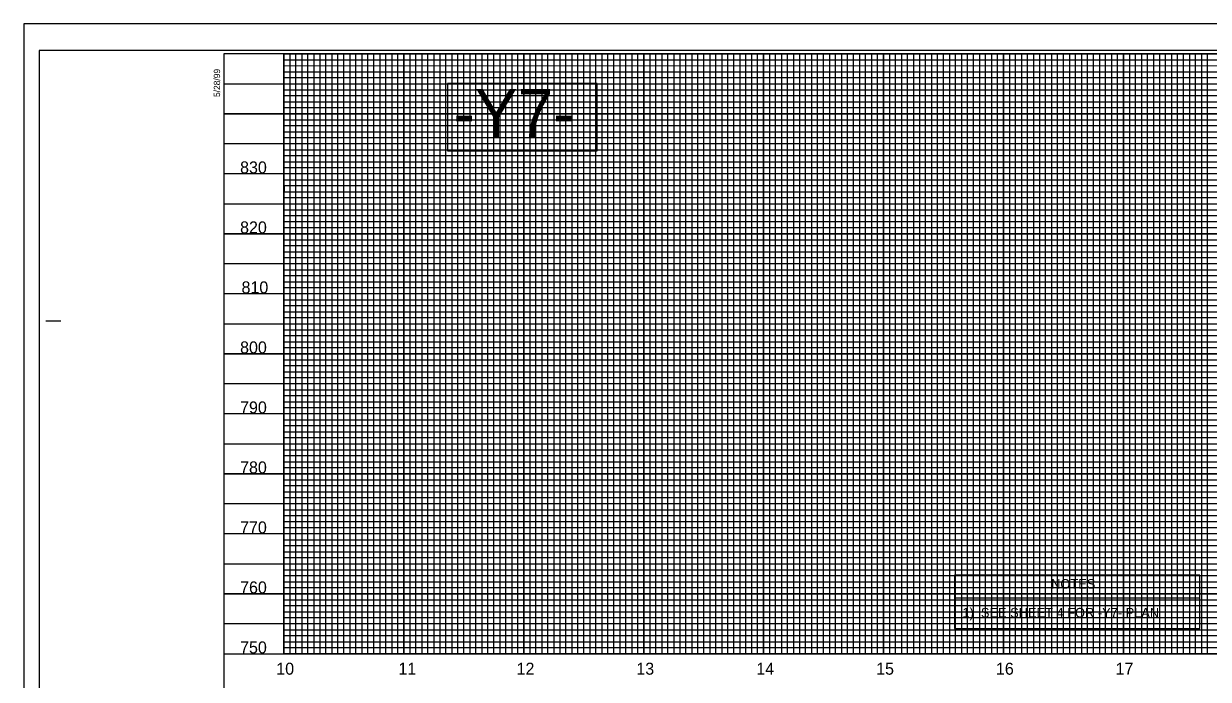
# Model space of a CAD drawing. Extents: x 600491 to 602382, y -54561 to -53461.
# Drawn here: x 600491 to 601479, y -54007 to -53461 of the extents above; entities that cross this region are included whole.
import ezdxf

# ---------------------------------------------------------------- set-up
doc = ezdxf.new("R2010")
doc.units = 0
for name, color, linetype in [('Default', 7, 'Continuous'), ('Exist Vertical Profile Horizontal Axis Label Major', 7, 'Continuous'), ('Exist Vertical Profile Vertical Axis Label', 7, 'Continuous'), ('Prop DSN Text', 7, 'Continuous'), ('Prop Grid Mask', 7, 'Continuous'), ('Prop VPI Label', 7, 'Continuous'), ('Sheet Cutting Line CELL', 7, 'Continuous'), ('Sheet DOT Grid CELL', 7, 'Continuous'), ('Sheet Layout Profile Border Port 1', 7, 'Continuous'), ('Sheet Plot Border Inside CELL', 7, 'Continuous'), ('Sheet Plot Border Outside CELL', 7, 'Continuous'), ('Sheet Profile CELL', 7, 'Continuous'), ('Sheet Profile Grid Major CELL', 7, 'Continuous'), ('Sheet Profile Grid Middle CELL', 7, 'Continuous'), ('Sheet Profile Grid Minor CELL', 7, 'Continuous')]:
    doc.layers.add(name, color=color, linetype=linetype)

msp = doc.modelspace()

# ---------------------------------------------------------------- linework, layer by layer
at = {"layer": 'Default'}
msp.add_lwpolyline([(600708.27, -53985.99), (601508.27, -53985.99), (601508.27, -53485.99), (600708.27, -53485.99)], close=True, dxfattribs=at)
at = {"layer": 'Prop Grid Mask'}
msp.add_line((601108.22, -53485.99), (601208.22, -53485.99), dxfattribs=at)
for points in [[(600844.71, -53566.95), (600969.5, -53566.95), (600969.5, -53510.89), (600844.71, -53510.89)], [(601267.49, -53964.91), (601471.84, -53964.91), (601471.84, -53920.63), (601267.49, -53920.63)], [(601267.49, -53939.34), (601471.84, -53939.34), (601471.84, -53920.63), (601267.49, -53920.63)]]:
    msp.add_lwpolyline(points, close=True, dxfattribs=at)
at = {"layer": 'Sheet Cutting Line CELL'}
for p, q in [((602175.27, -53460.99), (600491.27, -53460.99)), ((600491.27, -53460.99), (600491.27, -54560.99))]:
    msp.add_line(p, q, dxfattribs=at)
at = {"layer": 'Sheet DOT Grid CELL'}
for p, q in [((600708.27, -53985.99), (600708.27, -53485.99)), ((600758.27, -53985.99), (600758.27, -53485.99)), ((600808.27, -53985.99), (600808.27, -53485.99)), ((600858.27, -53985.99), (600858.27, -53485.99)), ((600908.27, -53985.99), (600908.27, -53485.99)), ((600958.27, -53985.99), (600958.27, -53485.99)), ((601008.27, -53985.99), (601008.27, -53485.99)), ((601058.27, -53985.99), (601058.27, -53485.99)), ((601108.27, -53985.99), (601108.27, -53485.99)), ((601158.27, -53985.99), (601158.27, -53485.99)), ((601208.27, -53985.99), (601208.27, -53485.99)), ((601258.27, -53985.99), (601258.27, -53485.99)), ((601308.27, -53985.99), (601308.27, -53485.99)), ((601358.27, -53985.99), (601358.27, -53485.99)), ((601408.27, -53985.99), (601408.27, -53485.99)), ((601458.27, -53985.99), (601458.27, -53485.99)), ((601958.22, -53535.99), (600658.27, -53535.99)), ((601958.22, -53585.99), (600658.27, -53585.99)), ((602158.27, -53635.99), (600658.27, -53635.99)), ((602158.27, -53685.99), (600658.27, -53685.99)), ((602158.27, -53735.99), (600658.27, -53735.99)), ((602158.27, -53785.99), (600658.27, -53785.99)), ((602158.27, -53835.99), (600658.27, -53835.99)), ((602158.27, -53885.99), (600658.27, -53885.99)), ((602158.27, -53935.99), (600658.27, -53935.99))]:
    msp.add_line(p, q, dxfattribs=at)
at = {"layer": 'Sheet Layout Profile Border Port 1'}
msp.add_lwpolyline([(601508.27, -53985.99), (600708.27, -53985.99), (600708.27, -53485.99), (601508.27, -53485.99)], close=True, dxfattribs=at)
at = {"layer": 'Sheet Plot Border Inside CELL'}
msp.add_lwpolyline([(600504.27, -54538.54), (602170.77, -54538.54), (602170.77, -53483.44), (600504.27, -53483.44)], close=True, dxfattribs=at)
at = {"layer": 'Sheet Plot Border Outside CELL'}
msp.add_lwpolyline([(600491.27, -54560.99), (602175.27, -54560.99), (602175.27, -53460.99), (600491.27, -53460.99)], close=True, dxfattribs=at)
at = {"layer": 'Sheet Profile CELL'}
for p, q in [((600509.77, -53708.49), (600522.27, -53708.49)), ((600658.27, -53985.99), (602158.27, -53985.99))]:
    msp.add_line(p, q, dxfattribs=at)
msp.add_lwpolyline([(602158.27, -53485.99), (600658.27, -53485.99), (600658.27, -54535.99), (602158.27, -54535.99)], close=True, dxfattribs=at)
at = {"layer": 'Sheet Profile Grid Major CELL'}
for points in [[(600708.27, -53485.99), (600708.27, -53985.99), (600758.27, -53985.99), (600758.27, -53485.99), (600808.27, -53485.99), (600808.27, -53985.99), (600858.27, -53985.99), (600858.27, -53485.99), (600908.27, -53485.99), (600908.27, -53985.99), (600958.27, -53985.99), (600958.27, -53485.99), (601008.27, -53485.99), (601008.27, -53985.99), (601058.27, -53985.99), (601058.27, -53485.99), (601108.27, -53485.99), (601108.27, -53985.99), (601158.27, -53985.99), (601158.27, -53485.99), (601208.27, -53485.99), (601208.27, -53985.99), (601258.27, -53985.99), (601258.27, -53485.99), (601308.27, -53485.99), (601308.27, -53985.99), (601358.27, -53985.99), (601358.27, -53485.99), (601408.27, -53485.99), (601408.27, -53985.99), (601458.27, -53985.99), (601458.27, -53485.99), (601508.27, -53485.99)], [(600658.27, -53535.99), (601958.27, -53535.99)], [(601958.27, -53585.99), (600658.27, -53585.99), (600658.27, -53635.99), (602158.27, -53635.99)], [(602158.27, -53685.99), (600658.27, -53685.99), (600658.27, -53735.99), (602158.27, -53735.99)], [(602158.27, -53785.99), (600658.27, -53785.99), (600658.27, -53835.99), (602158.27, -53835.99)], [(602158.27, -53885.99), (600658.27, -53885.99), (600658.27, -53885.99), (600658.27, -53935.99), (602158.27, -53935.99)]]:
    msp.add_lwpolyline(points, dxfattribs=at)
at = {"layer": 'Sheet Profile Grid Middle CELL'}
msp.add_line((600658.27, -53510.99), (601958.22, -53510.99), dxfattribs=at)
for points in [[(600733.27, -53485.99), (600733.27, -53985.99), (600783.27, -53985.99), (600783.27, -53485.99), (600833.27, -53485.99), (600833.27, -53985.99), (600883.27, -53985.99), (600883.27, -53485.99), (600933.27, -53485.99), (600933.27, -53985.99), (600983.27, -53985.99), (600983.27, -53485.99), (601033.27, -53485.99), (601033.27, -53985.99), (601083.27, -53985.99), (601083.27, -53485.99), (601133.27, -53485.99), (601133.27, -53985.99), (601183.27, -53985.99), (601183.27, -53485.99), (601233.27, -53485.99), (601233.27, -53985.99), (601283.27, -53985.99), (601283.27, -53985.99), (601283.27, -53485.99), (601333.27, -53485.99), (601333.27, -53985.99), (601383.27, -53985.99), (601383.27, -53485.99), (601433.27, -53485.99), (601433.27, -53985.99), (601483.27, -53985.99)], [(601958.27, -53560.99), (600658.27, -53560.99), (600658.27, -53610.99), (601958.27, -53610.99)], [(602158.27, -53660.99), (600658.27, -53660.99), (600658.27, -53710.99), (601983.27, -53710.99)], [(602158.27, -53760.99), (600658.27, -53760.99), (600658.27, -53810.99), (602158.27, -53810.99)], [(602158.27, -53860.99), (600658.27, -53860.99), (600658.27, -53910.99), (602158.27, -53910.99)], [(602158.27, -53960.99), (600658.27, -53960.99)]]:
    msp.add_lwpolyline(points, dxfattribs=at)
at = {"layer": 'Sheet Profile Grid Minor CELL'}
for p, q in [((600708.27, -53490.99), (601958.27, -53490.99)), ((600708.27, -53495.99), (600708.27, -53495.99)), ((601958.27, -53495.99), (600708.27, -53496.34)), ((600708.27, -53500.99), (601958.27, -53500.99)), ((601958.22, -53620.99), (600708.27, -53620.99)), ((602108.27, -53625.99), (600708.27, -53625.99)), ((602108.27, -53630.99), (600708.27, -53630.99)), ((600708.27, -53640.99), (602108.27, -53640.99)), ((602108.27, -53645.99), (600708.27, -53645.99)), ((600708.27, -53650.99), (602108.27, -53650.99)), ((602108.27, -53670.99), (600708.27, -53670.99)), ((600708.27, -53675.99), (602108.27, -53675.99)), ((602108.27, -53695.99), (600708.27, -53695.99)), ((600708.27, -53700.99), (602108.27, -53700.99)), ((602108.27, -53720.99), (600708.27, -53720.99)), ((600708.27, -53725.99), (602108.27, -53725.99)), ((602108.27, -53730.99), (600708.27, -53730.99)), ((600708.27, -53740.99), (602108.27, -53740.99)), ((602108.27, -53745.99), (600708.27, -53745.99)), ((600708.27, -53750.99), (602108.27, -53750.99)), ((602108.27, -53755.99), (600708.27, -53755.99)), ((600708.27, -53765.99), (602108.27, -53765.99)), ((602108.27, -53770.99), (600708.27, -53770.99)), ((600708.27, -53775.99), (602108.27, -53775.99)), ((602108.27, -53780.99), (600708.27, -53780.99)), ((600708.27, -53790.99), (602108.27, -53790.99)), ((602108.27, -53795.99), (600708.27, -53795.99)), ((600708.27, -53800.99), (602108.27, -53800.99)), ((602108.27, -53805.99), (600708.27, -53805.99)), ((600708.27, -53815.99), (602108.27, -53815.99)), ((602108.27, -53820.99), (600708.27, -53820.99)), ((600708.27, -53825.99), (602108.27, -53825.99)), ((602108.27, -53830.99), (600708.27, -53830.99)), ((600708.27, -53840.99), (602108.27, -53840.99)), ((602108.27, -53845.99), (600708.27, -53845.99)), ((600708.27, -53850.99), (602108.27, -53850.99)), ((602108.27, -53855.99), (600708.27, -53855.99)), ((600708.27, -53865.99), (602108.27, -53865.99)), ((602108.27, -53870.99), (600708.27, -53870.99)), ((602108.27, -53875.99), (600708.27, -53875.99)), ((602108.27, -53880.99), (600708.27, -53880.99)), ((600708.27, -53890.99), (602108.27, -53890.99)), ((602108.27, -53895.99), (600708.27, -53895.99)), ((600708.27, -53900.99), (602108.27, -53900.99)), ((602108.27, -53905.99), (600708.27, -53905.99)), ((600708.27, -53915.99), (602108.27, -53915.99)), ((602108.27, -53920.99), (600708.27, -53920.99)), ((600708.27, -53925.99), (602108.27, -53925.99)), ((602108.27, -53930.99), (600708.27, -53930.99)), ((600708.27, -53940.99), (602108.27, -53940.99)), ((602108.27, -53945.99), (600708.27, -53945.99)), ((600708.27, -53950.99), (602108.27, -53950.99)), ((602108.27, -53955.99), (600708.27, -53955.99)), ((600708.27, -53965.99), (602108.27, -53965.99)), ((602108.27, -53970.99), (600708.27, -53970.99)), ((600708.27, -53975.99), (602108.27, -53975.99))]:
    msp.add_line(p, q, dxfattribs=at)
for points in [[(600713.27, -53485.99), (600713.27, -53985.99), (600718.27, -53985.99), (600718.27, -53485.99), (600723.27, -53485.99), (600723.27, -53985.99), (600728.27, -53985.99), (600728.27, -53485.99), (600738.27, -53485.99), (600738.27, -53985.99), (600743.27, -53985.99), (600743.27, -53485.99), (600748.27, -53485.99), (600748.27, -53985.99), (600753.27, -53985.99), (600763.27, -53985.99), (600768.27, -53985.99), (600768.27, -53485.99), (600773.27, -53485.99), (600773.27, -53985.99), (600778.27, -53985.99), (600778.27, -53485.99), (600788.27, -53485.99), (600788.27, -53985.99), (600793.27, -53985.99), (600793.27, -53485.99), (600798.27, -53485.99), (600798.27, -53985.99), (600803.27, -53985.99), (600803.27, -53485.99), (600813.27, -53485.99), (600813.27, -53985.99), (600818.27, -53985.99), (600818.27, -53485.99), (600823.27, -53485.99), (600823.27, -53985.99), (600828.27, -53985.99), (600828.27, -53485.99), (600838.27, -53485.99), (600838.27, -53985.99), (600843.27, -53985.99), (600843.27, -53485.99), (600848.27, -53485.99), (600848.27, -53985.99), (600853.27, -53985.99), (600853.27, -53485.99), (600863.27, -53485.99), (600863.27, -53985.99), (600868.27, -53985.99), (600868.27, -53485.99), (600873.27, -53485.99), (600873.27, -53985.99), (600878.27, -53985.99), (600878.27, -53485.99), (600888.27, -53485.99), (600888.27, -53985.99), (600893.27, -53985.99), (600893.27, -53485.99), (600898.27, -53485.99), (600898.27, -53985.99), (600903.27, -53985.99), (600903.27, -53485.99), (600913.27, -53485.99), (600913.27, -53985.99), (600918.27, -53985.99), (600918.27, -53485.99), (600923.27, -53485.99), (600923.27, -53985.99)], [(600753.27, -53985.99), (600753.27, -53485.99), (600763.27, -53485.99), (600763.27, -53985.99)], [(600923.27, -53985.99), (600928.27, -53985.99), (600928.27, -53485.99), (600938.27, -53485.99), (600938.27, -53985.99), (600943.27, -53985.99), (600943.27, -53485.99), (600948.27, -53485.99), (600948.27, -53985.99), (600953.27, -53985.99), (600953.27, -53485.99), (600963.27, -53485.99), (600963.27, -53985.99), (600968.27, -53985.99), (600968.27, -53485.99), (600973.27, -53485.99), (600973.27, -53985.99), (600978.27, -53985.99), (600978.27, -53485.99), (600988.27, -53485.99), (600988.27, -53985.99), (600993.27, -53985.99), (600993.27, -53485.99), (600998.27, -53485.99), (600998.27, -53985.99), (601003.27, -53985.99), (601003.27, -53485.99), (601013.27, -53485.99), (601013.27, -53985.99), (601018.27, -53985.99), (601018.27, -53485.99), (601023.27, -53485.99), (601023.27, -53985.99), (601028.27, -53985.99), (601028.27, -53485.99), (601038.27, -53485.99), (601038.27, -53985.99), (601043.27, -53985.99), (601043.27, -53485.99), (601048.27, -53485.99), (601048.27, -53985.99), (601053.27, -53985.99), (601053.27, -53485.99), (601063.27, -53485.99), (601063.27, -53985.99), (601068.27, -53985.99), (601068.27, -53485.99), (601073.27, -53485.99), (601073.27, -53985.99), (601078.27, -53985.99), (601078.27, -53485.99), (601088.27, -53485.99), (601088.27, -53985.99), (601093.27, -53985.99), (601093.27, -53485.99), (601098.27, -53485.99), (601098.27, -53985.99), (601103.27, -53985.99), (601103.27, -53485.99), (601113.27, -53485.99), (601113.27, -53985.99), (601118.27, -53985.99), (601118.27, -53485.99), (601123.27, -53485.99), (601123.27, -53985.99), (601128.27, -53985.99), (601128.27, -53485.99), (601138.27, -53485.99), (601138.27, -53985.99), (601143.27, -53985.99), (601143.27, -53485.99), (601148.27, -53485.99), (601148.27, -53985.99), (601153.27, -53985.99), (601153.27, -53485.99), (601163.27, -53485.99), (601163.27, -53985.99), (601168.27, -53985.99), (601168.27, -53485.99), (601173.27, -53485.99), (601173.27, -53985.99), (601178.27, -53985.99), (601178.27, -53485.99), (601188.27, -53485.99), (601188.27, -53985.99), (601193.27, -53985.99), (601193.27, -53485.99), (601198.27, -53485.99), (601198.27, -53985.99), (601203.27, -53985.99), (601203.27, -53485.99), (601213.27, -53485.99), (601213.27, -53985.99), (601218.27, -53985.99), (601218.27, -53485.99), (601223.27, -53485.99), (601223.27, -53985.99), (601228.27, -53985.99), (601228.27, -53485.99), (601238.27, -53485.99)], [(601238.27, -53485.99), (601238.27, -53985.99), (601243.27, -53985.99), (601243.27, -53485.99), (601248.27, -53485.99), (601248.27, -53985.99), (601253.27, -53985.99), (601253.27, -53485.99), (601263.27, -53485.99), (601263.27, -53985.99), (601268.27, -53985.99), (601268.27, -53485.99), (601273.27, -53485.99), (601273.27, -53985.99), (601278.27, -53985.99), (601278.27, -53485.99), (601288.27, -53485.99), (601288.27, -53985.99), (601293.27, -53985.99), (601293.27, -53485.99), (601298.27, -53485.99), (601298.27, -53985.99), (601303.27, -53985.99), (601303.27, -53485.99), (601313.27, -53485.99), (601313.27, -53985.99), (601318.27, -53985.99), (601318.27, -53485.99), (601323.27, -53485.99), (601323.27, -53985.99), (601328.27, -53985.99), (601328.27, -53485.99), (601338.27, -53485.99), (601338.27, -53985.99), (601343.27, -53985.99), (601343.27, -53485.99), (601348.27, -53485.99), (601348.27, -53985.99), (601353.27, -53985.99), (601353.27, -53485.99), (601363.27, -53485.99), (601363.27, -53985.99), (601363.27, -53985.99), (601368.27, -53985.99), (601368.27, -53485.99), (601373.27, -53485.99), (601373.27, -53985.99), (601378.27, -53985.99), (601378.27, -53485.99), (601388.27, -53485.99), (601388.27, -53985.99), (601393.27, -53985.99), (601393.27, -53485.99), (601398.27, -53485.99), (601398.27, -53985.99), (601403.27, -53985.99), (601403.27, -53485.99), (601413.27, -53485.99), (601413.27, -53985.99), (601418.27, -53985.99), (601418.27, -53485.99), (601423.27, -53485.99), (601423.27, -53985.99), (601428.27, -53985.99), (601428.27, -53485.99), (601438.27, -53485.99), (601438.27, -53985.99), (601443.27, -53985.99), (601443.27, -53485.99), (601448.27, -53485.99), (601448.27, -53985.99), (601453.27, -53985.99), (601453.27, -53485.99), (601463.27, -53485.99), (601463.27, -53985.99), (601468.27, -53985.99), (601468.27, -53485.99), (601473.27, -53485.99), (601473.27, -53985.99), (601478.27, -53985.99), (601478.27, -53485.99), (601488.27, -53485.99)], [(601958.27, -53505.99), (600708.27, -53505.99), (600708.27, -53515.99), (601958.27, -53515.99)], [(601958.22, -53520.99), (600708.27, -53520.99), (600708.27, -53525.99), (601958.27, -53525.99)], [(601958.27, -53530.99), (600708.27, -53530.99), (600708.27, -53540.99), (601958.27, -53540.99)], [(601958.27, -53545.99), (600708.27, -53545.99), (600708.27, -53550.99), (601958.27, -53550.99)], [(601958.27, -53555.99), (600708.27, -53555.99), (600708.27, -53565.99), (601958.27, -53565.99)], [(601958.27, -53570.99), (600708.27, -53570.99), (600708.27, -53575.99), (601958.27, -53575.99)], [(601958.27, -53580.99), (600708.27, -53580.99), (600708.27, -53590.99), (601958.27, -53590.99)], [(601958.27, -53596.09), (600708.37, -53596.09), (600708.37, -53600.99), (601958.27, -53600.99)], [(601958.27, -53605.99), (600708.27, -53605.99), (600708.27, -53615.99), (601958.27, -53615.99)], [(602108.27, -53655.99), (600708.27, -53655.99), (600708.27, -53665.99), (602108.27, -53665.99)], [(602108.27, -53680.99), (600708.27, -53680.99), (600708.27, -53690.99), (602108.27, -53690.99)], [(602108.27, -53705.99), (600708.27, -53705.99), (600708.27, -53715.99), (602108.27, -53715.99)], [(602108.27, -53980.99), (600708.27, -53980.99)]]:
    msp.add_lwpolyline(points, dxfattribs=at)

# ---------------------------------------------------------------- texts
at = {"layer": 'Exist Vertical Profile Horizontal Axis Label Major'}
for s, p in [('10', (600701.86, -54003.49)), ('11', (600803.7, -54003.49)), ('12', (600902.24, -54003.49)), ('13', (601002.08, -54003.49)), ('14', (601102.14, -54003.49)), ('15', (601202.06, -54003.49)), ('16', (601301.94, -54003.49)), ('17', (601401.68, -54003.49))]:
    msp.add_text(s, height=10, dxfattribs=at).set_placement(p)
at = {"layer": 'Exist Vertical Profile Vertical Axis Label'}
for s, p in [('830', (600671.7, -53585.74)), ('820', (600671.7, -53635.74)), ('810', (600672.9, -53685.74)), ('800', (600671.7, -53735.74)), ('790', (600671.7, -53785.74)), ('780', (600671.7, -53835.74)), ('770', (600671.7, -53885.74)), ('760', (600671.7, -53935.74)), ('750', (600671.7, -53985.74))]:
    msp.add_text(s, height=10, dxfattribs=at).set_placement(p)
at = {"layer": 'Prop DSN Text'}
for s, p in [('NOTES', (601347.92, -53931.82)), ('1)  SEE SHEET 4 FOR -Y7- PLAN', (601273.97, -53955.82))]:
    msp.add_text(s, height=8, dxfattribs=at).set_placement(p)
at = {"layer": 'Prop VPI Label'}
msp.add_text('-Y7-', height=40, dxfattribs=at).set_placement((600849.61, -53555.44))
at = {"layer": 'Sheet Profile CELL'}
msp.add_text('5/28/99', height=5.25, rotation=90, dxfattribs=at).set_placement((600655.04, -53522.08))

doc.saveas('drawing.dxf')
